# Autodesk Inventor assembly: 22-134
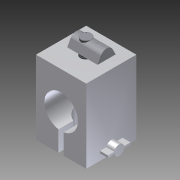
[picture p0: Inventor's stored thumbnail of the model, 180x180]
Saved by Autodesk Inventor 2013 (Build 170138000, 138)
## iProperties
Created: 2004-11
Part Number: 22-134
Document SubType Name: Assembly
Designer: Autodesk, Inc.
Manufacturer: Standard
Standards Organization: Custom
Description: SLIDE COLLAR
Vendor: PARKER IPS
Catalog Web Link: http://www.parker.com/ead/cm1.asp?cmid=809
Mass: 78.0759 g
Surface Area: 169.544 cm^2
Volume: 58.5257 cm^3
Density: 1.33405 g/cm^3
CAGE: 1LJX3
Dept. ID: Product Design
Description #2: ---
Finish #1: ---
Finish #2: ---
Material ID: ---
Project Number: ---
Author: Autodesk, Inc.
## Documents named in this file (6)
- Z:\_DATEN\Test Station\Components\22-134.iam
- Z:\_DATEN\Test Station\Components\24-120-8.ipt
- Z:\_DATEN\Test Station\Components\20-058.ipt
- Z:\_DATEN\Test Station\Components\22-134.ipt
- C:\Users\kelleyb.ADS\Desktop\Samples MIGRATED 2009 224 RTM_1\Standard Parts\Test Station Content\Fastners\2X-YYY-ZZ IPS Screws.ipt
- C:\Users\kelleyb.ADS\Desktop\Samples MIGRATED 2009 224 RTM_1\Standard Parts\Test Station Content\Fastners\20-XXX TSlot Nuts.ipt
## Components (3 placed, 3 different names)
1. 22-134:1 — Insert:1, Mate:1, Angle:1
2. 24-120-8:1 — Insert:1, Mate:2
3. 20-058:1 — Mate:1, Mate:2, Angle:1
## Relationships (4: Mate 2, Insert 1, Angle 1)
- Insert:1: 22-134:1 ↔ 24-120-8:1
- Mate:1: 22-134:1 ↔ 20-058:1
- Mate:2: 24-120-8:1 ↔ 20-058:1
- Angle:1: 22-134:1 ↔ 20-058:1
